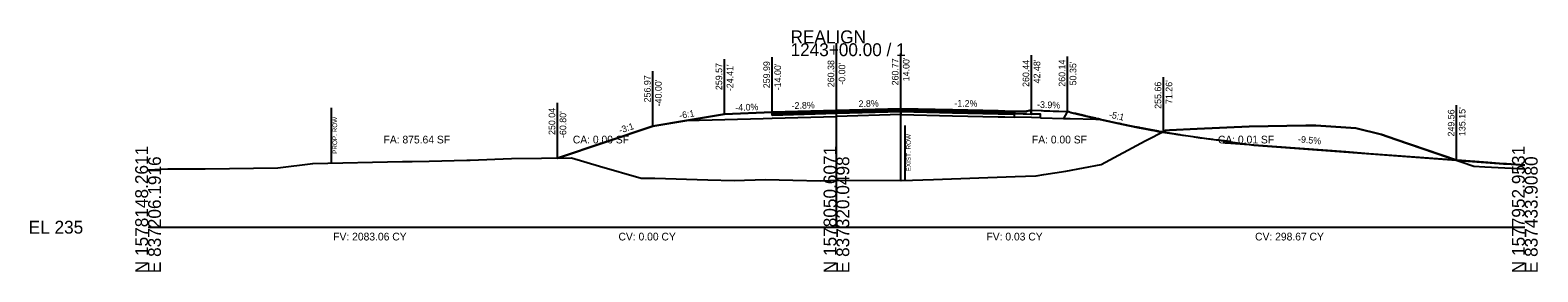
# Model space of a CAD drawing. Extents: x -26 to 6303, y -16 to 9563.
# Drawn here: x 1974.3 to 2302.8, y 2990.3 to 3042.8 of the extents above; entities that cross this region are included whole.
import ezdxf

# ---------------------------------------------------------------- set-up
doc = ezdxf.new("R2010")
doc.units = 0
for name, color, linetype in [('ASPHALT_19MM1', 7, 'Continuous'), ('ASPHALT_9_5MM1', 7, 'Continuous'), ('CONST_DCH', 7, 'Continuous'), ('CONST_LV3', 7, 'Continuous'), ('Default', 7, 'Continuous'), ('Draft_XS_Grid', 7, 'Continuous'), ('DTM_P_FINISHED_GRADE', 7, 'Continuous'), ('DTM_P_FINISHED_GRADE2', 7, 'Continuous'), ('DTM_TEMP_DROP', 7, 'Continuous'), ('DTM_X_GROUND', 7, 'Continuous'), ('TRANS_EOP_PAVED', 7, 'Continuous'), ('TRANS_PAVED_SHOULDERS', 7, 'Continuous'), ('XS_CELL', 7, 'Continuous'), ('XS_M_SHAPES_EARTHWORK', 7, 'Continuous'), ('XS_P_ASPHALT', 7, 'Continuous'), ('XS_P_CONCRETE', 7, 'Continuous'), ('XS_P_GROUND', 7, 'Continuous'), ('XS_P_ROW', 7, 'Continuous'), ('XS_P_SHOULDER', 7, 'Continuous'), ('XS_P_SUBGRADE_GRANULAR', 7, 'Continuous'), ('XS_P_SUBGRADE_GRANULAR_B', 7, 'Continuous'), ('XS_P_TX_CLEARZONE', 7, 'Continuous'), ('XS_P_TX_FS_BS', 7, 'Continuous'), ('XS_SHEET_EW_TX_AREA', 7, 'Continuous'), ('XS_SHEET_EW_TX_VOLUME', 7, 'Continuous'), ('XS_X_ROW', 7, 'Continuous')]:
    doc.layers.add(name, color=color, linetype=linetype)

msp = doc.modelspace()

# ---------------------------------------------------------------- linework, layer by layer
at = {"layer": 'ASPHALT_19MM1'}
for points in [[(2136, 3024.66), (2136, 3024.39), (2150, 3024.78), (2150, 3024.78), (2164, 3025.17), (2164, 3025.17), (2164, 3025.44), (2164, 3025.44), (2164, 3025.44), (2150, 3025.05), (2150, 3025.05), (2136, 3024.66), (2136, 3024.66)], [(2164, 3025.44), (2164, 3025.17), (2175.27, 3024.91), (2185.24, 3024.68), (2185.97, 3024.66), (2186.13, 3024.66), (2186.44, 3024.65), (2186.73, 3024.64), (2188.8, 3024.59), (2188.8, 3024.86), (2186.73, 3024.91), (2186.44, 3024.92), (2186.13, 3024.93), (2185.97, 3024.93), (2185.24, 3024.95), (2175.27, 3025.18), (2164, 3025.44)]]:
    msp.add_lwpolyline(points, dxfattribs=at)
at = {"layer": 'ASPHALT_9_5MM1'}
for points in [[(2136, 3024.99), (2136, 3024.86), (2150, 3025.26), (2150, 3025.26), (2164, 3025.65), (2164, 3025.65), (2164, 3025.77), (2164, 3025.77), (2164, 3025.77), (2150, 3025.38), (2150, 3025.38), (2136, 3024.99), (2136, 3024.99)], [(2164, 3025.77), (2164, 3025.65), (2175.27, 3025.39), (2185.24, 3025.16), (2185.97, 3025.14), (2186.13, 3025.14), (2186.44, 3025.13), (2186.73, 3025.12), (2188.8, 3025.07), (2188.8, 3025.2), (2186.73, 3025.25), (2186.44, 3025.25), (2186.13, 3025.26), (2185.97, 3025.27), (2185.24, 3025.28), (2175.27, 3025.52), (2164, 3025.77)]]:
    msp.add_lwpolyline(points, dxfattribs=at)
at = {"layer": 'CONST_LV3'}
for points in [[(2117.33, 3023.2), (2110, 3021.97)], [(2150, 3025.38), (2161.53, 3025.7), (2161.53, 3025.7), (2161.53, 3025.7), (2164, 3025.77), (2164, 3025.77), (2172.7, 3025.58)], [(2164, 3025.77), (2164, 3024.5), (2175.27, 3024.25), (2185.24, 3024.01), (2185.97, 3023.99), (2186.13, 3023.99), (2186.44, 3023.98), (2186.73, 3023.98), (2188.8, 3023.93), (2188.8, 3025.2), (2186.73, 3025.25), (2186.44, 3025.25), (2186.13, 3025.26), (2185.97, 3025.26), (2185.24, 3025.28), (2175.27, 3025.52), (2164, 3025.77)], [(2188.76, 3025.2), (2188.76, 3024.7), (2191.45, 3024.63), (2192.44, 3024.61), (2192.44, 3025.44), (2191.45, 3025.22), (2191.42, 3025.22), (2191.41, 3025.13), (2188.76, 3025.2)], [(2192.44, 3025.44), (2194.61, 3025.36), (2194.66, 3025.36), (2195.19, 3025.34), (2195.74, 3025.32), (2198.28, 3025.22), (2200.62, 3025.13)], [(2192.44, 3025.44), (2194.61, 3025.36), (2194.62, 3025.36), (2194.66, 3025.36), (2194.81, 3025.35), (2195.19, 3025.34), (2195.38, 3025.33), (2195.74, 3025.32), (2197.19, 3025.26), (2198.28, 3025.22), (2200.62, 3025.13), (2200.94, 3025.05), (2200.94, 3025.05), (2201.5, 3024.91), (2201.5, 3024.91), (2202.03, 3024.78), (2202.08, 3024.77), (2204.21, 3024.27), (2204.33, 3024.24), (2206.44, 3023.76), (2206.45, 3023.76), (2206.5, 3023.74), (2206.5, 3023.74), (2206.55, 3023.73), (2206.59, 3023.72), (2207.04, 3023.62), (2207.09, 3023.61), (2207.57, 3023.5), (2207.75, 3023.45), (2209.47, 3023.08), (2209.72, 3023.02), (2211.46, 3022.65), (2211.47, 3022.65), (2211.51, 3022.64), (2211.59, 3022.62), (2212, 3022.53), (2212.08, 3022.51), (2212.51, 3022.42), (2212.81, 3022.36), (2214.2, 3022.07), (2214.55, 3022), (2215.97, 3021.73), (2216.09, 3021.7), (2216.5, 3021.62), (2216.62, 3021.59), (2217.01, 3021.52), (2217.38, 3021.44), (2218.53, 3021.23), (2218.94, 3021.15), (2220.07, 3020.95), (2220.09, 3020.95), (2220.12, 3020.94), (2220.27, 3020.91), (2220.65, 3020.84), (2220.8, 3020.81), (2221.16, 3020.75), (2221.58, 3020.67), (2222.54, 3020.51), (2223, 3020.43), (2223.95, 3020.28), (2223.96, 3020.28), (2223.99, 3020.27), (2223.99, 3020.27), (2224, 3020.27), (2224.1, 3020.25), (2224.31, 3020.22), (2224.32, 3020.22), (2224.34, 3020.21), (2224.47, 3020.19), (2224.7, 3020.15), (2224.82, 3020.13), (2225.04, 3020.1), (2225.41, 3020.04), (2226.08, 3019.94), (2226.67, 3019.84), (2227.65, 3019.71), (2227.65, 3019.71), (2227.66, 3019.7), (2227.94, 3019.66), (2228.39, 3019.6), (2228.46, 3019.58), (2228.57, 3019.57), (2228.63, 3019.56), (2228.71, 3019.55), (2228.93, 3019.52), (2229.26, 3019.47), (2230.03, 3019.36), (2231.11, 3019.23), (2231.12, 3019.23), (2231.14, 3019.23), (2231.38, 3019.19), (2231.69, 3019.16), (2231.93, 3019.13), (2232.23, 3019.09), (2232.73, 3019.03), (2233.34, 3018.97), (2233.86, 3018.9), (2234.47, 3018.85), (2234.49, 3018.85), (2234.52, 3018.84), (2234.52, 3018.84), (2234.53, 3018.84), (2235.05, 3018.78), (2235.63, 3018.73)], [(2192.48, 3025.44), (2194.61, 3025.36), (2200.35, 3025.14), (2200.94, 3024.99), (2201.03, 3024.97), (2206.5, 3023.67), (2207.47, 3023.45), (2211.46, 3022.57), (2213.48, 3022.15), (2215.97, 3021.64), (2219.57, 3020.95), (2220.12, 3020.85), (2221.26, 3020.66)], [(2194.49, 3023.79), (2194.49, 3024.56), (2192.48, 3024.61)]]:
    msp.add_lwpolyline(points, dxfattribs=at)
at = {"layer": 'Default'}
msp.add_lwpolyline([(2172.7, 3025.58), (2177.43, 3025.47), (2179.56, 3025.42), (2180.27, 3025.4), (2184.97, 3025.29), (2185.87, 3025.27), (2186.04, 3025.26), (2186.14, 3025.26), (2186.22, 3025.26), (2187.09, 3025.24), (2187.29, 3025.23), (2188.2, 3025.21), (2188.28, 3025.21), (2188.76, 3025.2)], dxfattribs=at)
at = {"layer": 'DTM_P_FINISHED_GRADE'}
msp.add_lwpolyline([(2164, 3025.77), (2175.27, 3025.52), (2185.24, 3025.28), (2185.97, 3025.26), (2186.13, 3025.26), (2186.44, 3025.25), (2186.73, 3025.25), (2188.8, 3025.2)], dxfattribs=at)
at = {"layer": 'DTM_P_FINISHED_GRADE2'}
for points in [[(2089.2, 3015.04), (2089.2, 3015.04), (2110, 3021.97), (2125.59, 3024.57), (2136, 3024.99), (2150, 3025.38), (2164, 3025.77), (2176.92, 3025.48), (2185.97, 3025.26), (2186.13, 3025.26), (2186.44, 3025.25), (2186.73, 3025.25), (2188.8, 3025.2), (2189.63, 3025.18), (2191.47, 3025.13), (2191.47, 3025.17), (2191.47, 3025.22), (2192.13, 3025.36), (2192.48, 3025.44), (2194.61, 3025.36), (2200.35, 3025.14), (2201.2, 3024.93), (2207.47, 3023.45), (2209.52, 3023.02), (2213.48, 3022.15), (2218.64, 3021.14), (2219.57, 3020.95), (2220.12, 3020.85), (2221.26, 3020.66)], [(2285.15, 3014.56), (2285.86, 3014.51), (2286.61, 3014.45), (2295.34, 3013.81), (2295.76, 3013.77), (2295.98, 3013.76), (2296.01, 3013.76), (2300, 3013.47)]]:
    msp.add_lwpolyline(points, dxfattribs=at)
at = {"layer": 'DTM_X_GROUND'}
msp.add_lwpolyline([(2000, 3012.45), (2004.3, 3012.68), (2012.41, 3012.7), (2028.29, 3012.88), (2035.93, 3013.87), (2055.47, 3014.26), (2057.58, 3014.3), (2061.29, 3014.39), (2069.44, 3014.58), (2070.19, 3014.6), (2079.21, 3014.91), (2092.3, 3015.08), (2098.4, 3013.3), (2107.47, 3010.65), (2110.4, 3010.66), (2121.95, 3010.3), (2127.72, 3010.17), (2134.54, 3010.37), (2140.48, 3010.23), (2146.56, 3010.09), (2150.63, 3010.24), (2164.27, 3010.15), (2171.15, 3010.41), (2188.95, 3011.02), (2191.18, 3011.11), (2193.52, 3011.19), (2195.22, 3011.45), (2199.98, 3012.22), (2207.68, 3013.67), (2217.24, 3018.78), (2221.67, 3021.02), (2222.56, 3021.14), (2228.63, 3021.37), (2239.92, 3021.91), (2252.28, 3022.1), (2254.47, 3022.14), (2263.15, 3021.57), (2268.74, 3020.16), (2271.88, 3019.08), (2288.9, 3013.29), (2291.3, 3013.14), (2300, 3012.69)], dxfattribs=at)
at = {"layer": 'TRANS_PAVED_SHOULDERS'}
for points in [[(2136, 3024.86), (2136, 3024.66), (2150, 3025.05), (2150, 3025.05), (2164, 3025.44), (2164, 3025.44), (2164, 3025.65), (2164, 3025.65), (2164, 3025.65), (2150, 3025.26), (2150, 3025.26), (2136, 3024.86), (2136, 3024.86)], [(2164, 3025.65), (2164, 3025.44), (2175.27, 3025.18), (2185.24, 3024.95), (2185.97, 3024.93), (2186.13, 3024.93), (2186.44, 3024.92), (2186.73, 3024.91), (2188.8, 3024.86), (2188.8, 3025.07), (2186.73, 3025.12), (2186.44, 3025.13), (2186.13, 3025.14), (2185.97, 3025.14), (2185.24, 3025.16), (2175.27, 3025.39), (2164, 3025.65)]]:
    msp.add_lwpolyline(points, dxfattribs=at)
at = {"layer": 'XS_CELL'}
for p, q in [((2150, 3000), (2150, 3040)), ((2000, 3000), (2150, 3000)), ((2150, 3000), (2300, 3000))]:
    msp.add_line(p, q, dxfattribs=at)
at = {"layer": 'XS_M_SHAPES_EARTHWORK'}
msp.add_lwpolyline([(2089.2, 3015.04), (2092.3, 3015.08), (2098.4, 3013.3), (2107.47, 3010.65), (2110.4, 3010.66), (2121.95, 3010.3), (2127.72, 3010.17), (2134.54, 3010.37), (2140.48, 3010.23), (2146.56, 3010.09), (2150.63, 3010.24), (2164, 3010.16), (2164, 3025.17), (2150, 3024.78), (2136, 3024.39), (2136, 3024.66), (2136, 3024.86), (2136, 3024.99), (2125.59, 3024.57), (2117.33, 3023.2), (2110, 3021.97)], close=True, dxfattribs=at)
at = {"layer": 'XS_P_ASPHALT'}
msp.add_lwpolyline([(2164, 3025.77), (2175.27, 3025.52), (2185.24, 3025.28), (2185.97, 3025.26), (2186.13, 3025.26), (2186.44, 3025.25), (2186.73, 3025.25), (2188.8, 3025.2)], dxfattribs=at)
at = {"layer": 'XS_P_CONCRETE'}
msp.add_lwpolyline([(2188.8, 3025.2), (2188.8, 3024.7), (2192.48, 3024.61), (2192.48, 3025.44), (2191.47, 3025.22), (2191.47, 3025.13), (2188.8, 3025.2)], dxfattribs=at)
at = {"layer": 'XS_P_GROUND'}
for points in [[(2125.59, 3024.57), (2110, 3021.97), (2089.2, 3015.04)], [(2200.35, 3025.14), (2200.94, 3024.99), (2201.03, 3024.97), (2206.5, 3023.67), (2207.47, 3023.45), (2211.46, 3022.57), (2213.48, 3022.15), (2215.97, 3021.64), (2219.57, 3020.95), (2220.12, 3020.85), (2221.26, 3020.66)], [(2200.62, 3025.13), (2200.94, 3025.05), (2200.94, 3025.05), (2201.5, 3024.91), (2201.5, 3024.91), (2202.03, 3024.78), (2202.08, 3024.77), (2204.21, 3024.27), (2204.33, 3024.24), (2206.44, 3023.76), (2206.45, 3023.76), (2206.5, 3023.74), (2206.5, 3023.74), (2206.55, 3023.73), (2206.59, 3023.72), (2207.04, 3023.62), (2207.09, 3023.61), (2207.57, 3023.5), (2207.75, 3023.45), (2209.47, 3023.08), (2209.72, 3023.02), (2211.46, 3022.65), (2211.47, 3022.65), (2211.51, 3022.64), (2211.59, 3022.62), (2212, 3022.53), (2212.08, 3022.51), (2212.51, 3022.42), (2212.81, 3022.36), (2214.2, 3022.07), (2214.55, 3022), (2215.97, 3021.73), (2216.09, 3021.7), (2216.5, 3021.62), (2216.62, 3021.59), (2217.01, 3021.52), (2217.38, 3021.44), (2218.53, 3021.23), (2218.94, 3021.15), (2220.07, 3020.95), (2220.09, 3020.95), (2220.12, 3020.94), (2220.27, 3020.91), (2220.65, 3020.84), (2220.8, 3020.81), (2221.16, 3020.75), (2221.58, 3020.67), (2222.54, 3020.51), (2223, 3020.43), (2223.95, 3020.28), (2223.96, 3020.28), (2223.99, 3020.27), (2223.99, 3020.27), (2224, 3020.27), (2224.1, 3020.25), (2224.31, 3020.22), (2224.32, 3020.22), (2224.34, 3020.21), (2224.47, 3020.19), (2224.7, 3020.15), (2224.82, 3020.13), (2225.04, 3020.1), (2225.41, 3020.04), (2226.08, 3019.94), (2226.67, 3019.84), (2227.65, 3019.71), (2227.65, 3019.71), (2227.66, 3019.7), (2227.94, 3019.66), (2228.39, 3019.6), (2228.46, 3019.58), (2228.57, 3019.57), (2228.63, 3019.56), (2228.71, 3019.55), (2228.93, 3019.52), (2229.26, 3019.47), (2230.03, 3019.36), (2231.11, 3019.23), (2231.12, 3019.23), (2231.14, 3019.23), (2231.38, 3019.19), (2231.69, 3019.16), (2231.93, 3019.13), (2232.23, 3019.09), (2232.73, 3019.03), (2233.34, 3018.97), (2233.86, 3018.9), (2234.47, 3018.85), (2234.49, 3018.85), (2234.52, 3018.84), (2234.52, 3018.84), (2234.53, 3018.84), (2235.05, 3018.78), (2235.63, 3018.73)], [(2291.01, 3014.13), (2286, 3014.5), (2281, 3014.87), (2276, 3015.24), (2270.99, 3015.61), (2265.99, 3015.99), (2260.99, 3016.36), (2255.98, 3016.73), (2250.98, 3017.1), (2245.98, 3017.47), (2240.97, 3017.84), (2235.97, 3018.21), (2234.71, 3018.31), (2234.29, 3018.34)], [(2300, 3013.47), (2296.01, 3013.76), (2295.98, 3013.76), (2295.76, 3013.77), (2295.34, 3013.81), (2291.95, 3014.06), (2291.83, 3014.07), (2291.01, 3014.13), (2286.23, 3014.48), (2286, 3014.5), (2285.15, 3014.56)]]:
    msp.add_lwpolyline(points, dxfattribs=at)
at = {"layer": 'XS_P_ROW'}
msp.add_line((2040, 3013.95), (2040, 3025.95), dxfattribs=at)
at = {"layer": 'XS_P_SHOULDER'}
for points in [[(2125.59, 3024.57), (2125.59, 3024.57), (2136, 3024.99)], [(2192.48, 3025.44), (2194.61, 3025.36), (2200.35, 3025.14)]]:
    msp.add_lwpolyline(points, dxfattribs=at)
at = {"layer": 'XS_P_SUBGRADE_GRANULAR'}
for points in [[(2117.33, 3023.2), (2117.33, 3023.2), (2134, 3023.66), (2136, 3023.72), (2136, 3023.72)], [(2136, 3023.72), (2150, 3024.11), (2150, 3024.11)], [(2164, 3024.5), (2164, 3024.5), (2150, 3024.11)], [(2164, 3024.5), (2175.27, 3024.25), (2185.24, 3024.01), (2185.97, 3023.99), (2186.13, 3023.99), (2186.44, 3023.98), (2186.73, 3023.98), (2188.8, 3023.93)], [(2192.48, 3023.84), (2188.8, 3023.93)], [(2194.49, 3023.79), (2192.48, 3023.84)]]:
    msp.add_lwpolyline(points, dxfattribs=at)
at = {"layer": 'XS_P_SUBGRADE_GRANULAR_B'}
for points in [[(2194.49, 3023.79), (2194.61, 3023.79), (2199.48, 3023.67)], [(2200.35, 3025.14), (2200.23, 3024.96), (2199.48, 3023.67)], [(2199.48, 3023.67), (2200.94, 3023.63), (2206.5, 3023.47), (2207.54, 3023.44)]]:
    msp.add_lwpolyline(points, dxfattribs=at)
at = {"layer": 'XS_P_TX_CLEARZONE'}
for p, q in [((2125.59, 3024.57), (2125.59, 3036.57)), ((2136, 3024.99), (2136, 3036.99)), ((2150, 3025.38), (2150, 3037.38)), ((2164, 3025.77), (2164, 3037.77)), ((2192.48, 3025.44), (2192.48, 3037.44)), ((2200.35, 3025.14), (2200.35, 3037.14)), ((2110, 3021.97), (2110, 3033.97)), ((2221.26, 3020.66), (2221.26, 3032.66)), ((2089.2, 3015.04), (2089.2, 3027.04)), ((2285.15, 3014.56), (2285.15, 3026.56))]:
    msp.add_line(p, q, dxfattribs=at)
at = {"layer": 'XS_P_TX_FS_BS'}
for p, q in [((2221.04, 3020.69), (2240.97, 3017.84)), ((2240.97, 3017.84), (2285.15, 3014.56))]:
    msp.add_line(p, q, dxfattribs=at)
msp.add_lwpolyline([(2285.15, 3014.56), (2271.88, 3019.08), (2268.74, 3020.16), (2263.15, 3021.57), (2254.47, 3022.14), (2252.28, 3022.1), (2239.92, 3021.91), (2228.63, 3021.37), (2222.56, 3021.14), (2221.67, 3021.02), (2221.04, 3020.69)], dxfattribs=at)
at = {"layer": 'XS_X_ROW'}
msp.add_line((2164.98, 3010.15), (2164.98, 3022.15), dxfattribs=at)

# ---------------------------------------------------------------- texts
at = {"layer": 'CONST_DCH'}
for p in [(2163.92, 3025.65), (2135.92, 3024.87), (2149.92, 3025.26)]:
    msp.add_text('X', height=0.24, dxfattribs=at).set_placement(p)
at = {"layer": 'CONST_LV3'}
msp.add_text('X', height=0.24, dxfattribs=at).set_placement((2109.92, 3021.85))
at = {"layer": 'Draft_XS_Grid'}
msp.add_text('-', height=0.0001, dxfattribs=at).set_placement((2000, 3000))
at = {"layer": 'DTM_TEMP_DROP'}
for p in [(2200.55, 3025.01), (2221.18, 3020.54), (2089.12, 3014.92), (2285.07, 3014.44)]:
    msp.add_text('X', height=0.24, dxfattribs=at).set_placement(p)
at = {"layer": 'TRANS_EOP_PAVED'}
for p in [(2221.18, 3020.54), (2089.12, 3014.92), (2285.07, 3014.44)]:
    msp.add_text('X', height=0.24, dxfattribs=at).set_placement(p)
at = {"layer": 'XS_CELL'}
for s, p in [('REALIGN', (2140, 3040)), ('1243+00.00 / 1', (2140, 3037.2)), ('EL 235', (1974, 2998.6))]:
    msp.add_text(s, height=2.8, dxfattribs=at).set_placement(p)
for s, p in [('N 1578148.2611', (2000, 2990)), ('N 1578050.6071', (2150, 2990)), ('N 1577952.9531', (2300, 2990)), ('E 837206.1916', (2002.8, 2990)), ('E 837320.0498', (2152.8, 2990)), ('E 837433.9080', (2302.8, 2990))]:
    msp.add_text(s, height=2.8, rotation=90, dxfattribs=at).set_placement(p)
at = {"layer": 'XS_P_ROW'}
msp.add_text('PROP. ROW', height=1, rotation=90, dxfattribs=at).set_placement((2041.2, 3015.95))
at = {"layer": 'XS_P_SUBGRADE_GRANULAR'}
for p in [(2125.51, 3024.45), (2192.4, 3025.32), (2200.27, 3025.02)]:
    msp.add_text('X', height=0.24, dxfattribs=at).set_placement(p)
at = {"layer": 'XS_P_TX_CLEARZONE'}
for s, p in [('259.99', (2135.52, 3030.22)), ('260.38', (2149.52, 3030.45)), ("-0.00'", (2151.92, 3030.99)), ('260.77', (2163.52, 3030.84)), ("14.00'", (2165.92, 3031.74)), ('260.44', (2192, 3030.51)), ("42.48'", (2194.4, 3031.28)), ('260.14', (2199.87, 3030.56)), ("50.35'", (2202.27, 3030.86)), ('256.97', (2109.52, 3027.15)), ('259.57', (2125.11, 3029.82)), ("-24.41'", (2127.51, 3029.59)), ("-14.00'", (2137.92, 3029.78)), ("-40.00'", (2111.92, 3026.29)), ('255.66', (2220.78, 3025.75)), ("71.26'", (2223.18, 3026.79)), ('250.04', (2088.72, 3020.06)), ("135.15'", (2287.07, 3019.83)), ("-60.80'", (2091.12, 3019.4)), ('249.56', (2284.67, 3019.73))]:
    msp.add_text(s, height=1.44, rotation=90, dxfattribs=at).set_placement(p)
at = {"layer": 'XS_P_TX_FS_BS'}
for s, rotation, p in [('-4.0%', 2.2906, (2127.98, 3025.27)), ('-2.8%', 1.6039, (2140.25, 3025.71)), ('2.8%', 1.6039, (2154.84, 3026.12)), ('-1.2%', 359.3368, (2175.69, 3026.24)), ('-3.9%', 357.7565, (2193.7, 3026)), ('-3:1', 18.4332, (2102.87, 3020.35)), ('-6:1', 9.4642, (2115.87, 3023.56)), ('-5:1', 347.7768, (2209.3, 3023.86)), ('-9.5%', 354.5512, (2250.54, 3018.47))]:
    msp.add_text(s, height=1.44, rotation=rotation, dxfattribs=at).set_placement(p)
at = {"layer": 'XS_SHEET_EW_TX_AREA'}
for s, p in [('FA: 875.64 SF', (2051.32, 3018.22)), ('CA: 0.00 SF', (2092.56, 3018.22)), ('FA: 0.00 SF', (2192.6, 3018.22)), ('CA: 0.01 SF', (2233.12, 3018.22))]:
    msp.add_text(s, height=1.68, dxfattribs=at).set_placement(p)
at = {"layer": 'XS_SHEET_EW_TX_VOLUME'}
for s, p in [('FV: 2083.06 CY', (2040.35, 2997.12)), ('CV: 0.00 CY', (2102.51, 2997.12)), ('FV: 0.03 CY', (2182.69, 2997.12)), ('CV: 298.67 CY', (2241.23, 2997.12))]:
    msp.add_text(s, height=1.68, dxfattribs=at).set_placement(p)
at = {"layer": 'XS_X_ROW'}
msp.add_text('EXIST. ROW', height=1, rotation=90, dxfattribs=at).set_placement((2166.18, 3012.15))

doc.saveas('drawing.dxf')
